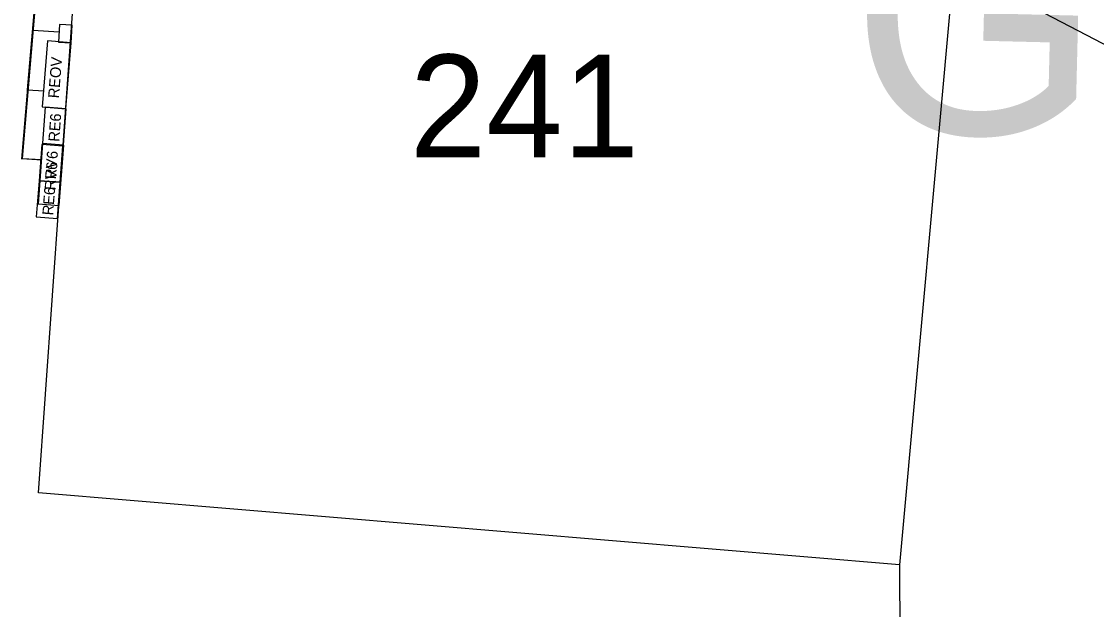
# Model space of a CAD drawing. Extents: x -670359 to -668019, y -978807 to -976674.
# Drawn here: x -669518.52 to -669500.74, y -977163.16 to -977153.43 of the extents above; entities that cross this region are included whole.
import ezdxf

# ---------------------------------------------------------------- set-up
doc = ezdxf.new("R2010")
doc.units = 0
for name, color, linetype in [('Hranice parcel', 7, 'Continuous'), ('Parcelní čísla', 7, 'Continuous'), ('SO 01-86-01', 7, 'Continuous'), ('Stávající', 7, 'Continuous'), ('Vnitřní kresba', 7, 'Continuous'), ('ŽBP', 7, 'Continuous')]:
    doc.layers.add(name, color=color, linetype=linetype)

msp = doc.modelspace()

# ---------------------------------------------------------------- linework, layer by layer
at = {"layer": 'Hranice parcel'}
for points in [[(-669518.24, -977161.23), (-669517.43, -977149.8)], [(-669503.1, -977152.51), (-669504, -977162.42)], [(-669504, -977162.42), (-669518.24, -977161.23)]]:
    msp.add_lwpolyline(points, dxfattribs=at)
at = {"layer": 'SO 01-86-01'}
for p, q in [((-669517.763, -977146.78), (-669518.52, -977155.707)), ((-669517.763, -977146.78), (-669518.507, -977155.699)), ((-669517.763, -977146.78), (-669518.424, -977154.562)), ((-669517.895, -977153.61), (-669518.331, -977153.581)), ((-669517.89, -977153.481), (-669517.906, -977153.771)), ((-669517.681, -977153.493), (-669517.89, -977153.481)), ((-669517.698, -977153.783), (-669517.681, -977153.493)), ((-669518.092, -977153.75), (-669518.181, -977154.842)), ((-669517.698, -977153.783), (-669518.092, -977153.75)), ((-669517.906, -977153.771), (-669517.698, -977153.783)), ((-669517.787, -977154.874), (-669517.698, -977153.783)), ((-669518.424, -977154.562), (-669518.147, -977154.579)), ((-669518.181, -977154.842), (-669517.787, -977154.874)), ((-669518.171, -977155.452), (-669518.244, -977156.45)), ((-669517.822, -977155.478), (-669518.171, -977155.452)), ((-669517.822, -977155.478), (-669518.171, -977155.452)), ((-669517.895, -977156.475), (-669517.822, -977155.478)), ((-669517.895, -977156.475), (-669517.822, -977155.478)), ((-669518.515, -977155.7), (-669518.186, -977155.718)), ((-669518.507, -977155.699), (-669518.183, -977155.713)), ((-669518.244, -977156.45), (-669517.895, -977156.475))]:
    msp.add_line(p, q, dxfattribs=at)
at = {"layer": 'Stávající'}
for p, q in [((-669518.129, -977154.848), (-669518.175, -977155.447)), ((-669517.78, -977154.875), (-669518.129, -977154.848)), ((-669517.826, -977155.473), (-669517.78, -977154.875)), ((-669518.184, -977155.467), (-669518.229, -977156.065)), ((-669517.835, -977155.493), (-669518.184, -977155.467)), ((-669518.175, -977155.447), (-669517.826, -977155.473)), ((-669517.88, -977156.091), (-669517.835, -977155.493)), ((-669518.229, -977156.065), (-669518.275, -977156.663)), ((-669517.88, -977156.091), (-669518.229, -977156.065)), ((-669518.229, -977156.065), (-669517.88, -977156.091)), ((-669517.926, -977156.69), (-669517.88, -977156.091)), ((-669518.275, -977156.663), (-669517.926, -977156.69))]:
    msp.add_line(p, q, dxfattribs=at)
at = {"layer": 'Vnitřní kresba'}
for points in [[(-669489.14, -977159.78), (-669503.1, -977152.51)], [(-669504, -977162.42), (-669503.98, -977166.02)]]:
    msp.add_lwpolyline(points, dxfattribs=at)

# ---------------------------------------------------------------- texts
at = {"layer": 'Parcelní čísla'}
msp.add_text('241', height=1.7, dxfattribs=at).set_placement((-669512.097, -977155.68))
at = {"layer": 'SO 01-86-01'}
for s, rotation, p in [('REOV', 85.3123, (-669517.902, -977154.707)), ('RV6', 85.8169, (-669517.959, -977156.226))]:
    msp.add_text(s, height=0.18, rotation=rotation, dxfattribs=at).set_placement(p)
at = {"layer": 'Stávající'}
for s, p in [('RE6', (-669517.897, -977155.426)), ('RV6', (-669517.952, -977156.045)), ('RE6', (-669517.997, -977156.643))]:
    msp.add_text(s, height=0.18, rotation=85.6742, dxfattribs=at).set_placement(p)
at = {"layer": 'ŽBP'}
msp.add_text('GB 701', height=3.9996, rotation=358.6082, dxfattribs=at).set_placement((-669504.851, -977155.244))

doc.saveas('drawing.dxf')
